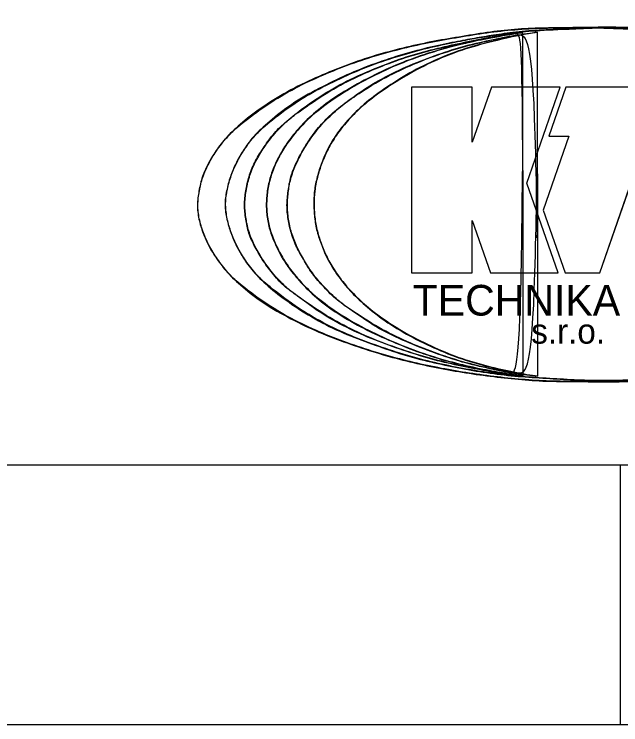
# Model space of a CAD drawing. Extents: x 25 to 46, y -90 to -60.3.
# Drawn here: x 37.705 to 40.036, y -79.8 to -77.068 of the extents above; entities that cross this region are included whole.
import ezdxf

# ---------------------------------------------------------------- set-up
doc = ezdxf.new("R2010")
doc.units = 0
doc.layers.add('_popis', color=7, linetype='Continuous')
doc.layers.add('Rozpiska_pole_6', color=7, linetype='Continuous')

msp = doc.modelspace()

# ---------------------------------------------------------------- linework, layer by layer
at = {"layer": '_popis'}
for p, q in [((39.2313, -77.3488), (39.2313, -78.0628)), ((39.465, -77.3488), (39.2313, -77.3488)), ((39.5386, -77.3488), (39.465, -77.5605)), ((39.465, -77.5605), (39.465, -77.3488)), ((39.8036, -77.3488), (39.5386, -77.3488)), ((39.675, -77.7182), (39.8036, -77.3488)), ((39.825, -77.3488), (39.7594, -77.5375)), ((40.2641, -77.3488), (39.825, -77.3488)), ((39.8369, -77.5375), (39.7381, -77.8213)), ((39.7594, -77.5375), (39.8369, -77.5375)), ((39.9551, -78.0628), (40.1379, -77.5375)), ((39.795, -78.0628), (39.675, -77.7182)), ((39.7381, -77.8213), (39.8222, -78.0628)), ((39.465, -78.0628), (39.465, -77.8616)), ((39.465, -77.8616), (39.535, -78.0628)), ((39.2313, -78.0628), (39.465, -78.0628)), ((39.535, -78.0628), (39.795, -78.0628)), ((39.8222, -78.0628), (39.9551, -78.0628))]:
    msp.add_line(p, q, dxfattribs=at)
for points in [[(39.2313, -77.3488), (39.2313, -78.0628), (39.465, -78.0628), (39.465, -77.8616), (39.535, -78.0628), (39.795, -78.0628), (39.675, -77.7182), (39.8036, -77.3488), (39.5386, -77.3488), (39.465, -77.5605), (39.465, -77.3488), (39.2313, -77.3488)], [(39.825, -77.3488), (39.7594, -77.5375), (39.8369, -77.5375), (39.7381, -77.8213), (39.8222, -78.0628), (39.9551, -78.0628), (40.1379, -77.5375), (40.1984, -77.5375), (40.2641, -77.3488), (39.825, -77.3488)]]:
    msp.add_lwpolyline(points, dxfattribs=at)
for points in [[(39.9639, -77.1182), (39.9235, -77.1188), (39.852, -77.1199), (39.7448, -77.1208), (39.642, -77.1242), (39.5347, -77.1357), (39.4277, -77.1537), (39.3201, -77.1713), (39.2128, -77.1946), (39.1051, -77.2223), (38.9975, -77.2573), (38.8906, -77.3005), (38.7817, -77.3493), (38.6736, -77.4136), (38.589, -77.4768), (38.5246, -77.5353), (38.4849, -77.5846), (38.452, -77.639), (38.4265, -77.6924), (38.4148, -77.7474), (38.4067, -77.8011), (38.4133, -77.8559), (38.4303, -77.9096), (38.4542, -77.9643), (38.4893, -78.0177), (38.5268, -78.0666), (38.5904, -78.1238), (38.6724, -78.1873), (38.7823, -78.2472), (38.8896, -78.2978), (38.9979, -78.3377), (39.1054, -78.3729), (39.2125, -78.4023), (39.3197, -78.4256), (39.427, -78.4454), (39.5348, -78.4603), (39.6419, -78.4721), (39.7493, -78.4805), (39.8565, -78.4792), (39.9639, -78.483), (40.0712, -78.4798), (40.1532, -78.4786), (40.1993, -78.4763), (40.2097, -78.4757)], [(39.9639, -77.1182), (39.8427, -77.1199), (39.7495, -77.1211), (39.6423, -77.1255), (39.5351, -77.1368), (39.4279, -77.1536), (39.3205, -77.1722), (39.2133, -77.1952), (39.1061, -77.2232), (38.9987, -77.2583), (38.8915, -77.3009), (38.7849, -77.3503), (38.6775, -77.4138), (38.5703, -77.4945), (38.5286, -77.5334), (38.4849, -77.5873), (38.4523, -77.6406), (38.4282, -77.6944), (38.4153, -77.7478), (38.4091, -77.8015), (38.4147, -77.8543), (38.431, -77.9085), (38.4551, -77.9623), (38.4888, -78.0156), (38.532, -78.0694), (38.5702, -78.1052), (38.6774, -78.1865), (38.7846, -78.2471), (38.8906, -78.2964), (38.9989, -78.3373), (39.1065, -78.3723), (39.2131, -78.4014), (39.3197, -78.425), (39.4275, -78.4446), (39.535, -78.4598), (39.6427, -78.4716), (39.7487, -78.4789), (39.8568, -78.4801), (39.9639, -78.4818), (40.0711, -78.4801), (40.1786, -78.4773), (40.2858, -78.4705), (40.3924, -78.4605), (40.4999, -78.4442), (40.6071, -78.4251), (40.7143, -78.401), (40.8218, -78.3713), (40.929, -78.336), (41.0362, -78.2945), (41.1428, -78.2446), (41.2508, -78.1813), (41.3585, -78.0978), (41.3905, -78.0692), (41.4326, -78.0159), (41.468, -77.9626), (41.4928, -77.9085), (41.5102, -77.8552), (41.5187, -77.8015), (41.5124, -77.748), (41.4939, -77.6942), (41.4698, -77.6394), (41.4378, -77.5872), (41.3924, -77.5334), (41.3593, -77.5009), (41.2509, -77.417), (41.1437, -77.3537), (41.0373, -77.3029), (40.9295, -77.2614), (40.8218, -77.2244), (40.7152, -77.1964), (40.6071, -77.1722), (40.4994, -77.1537), (40.3917, -77.1386), (40.2853, -77.125), (40.1784, -77.1211), (40.0713, -77.1192), (39.9639, -77.1182), (39.9639, -77.1182), (39.9639, -77.1182)], [(40.2097, -78.4757), (40.235, -78.4743), (40.296, -78.4699), (40.3931, -78.4618), (40.5, -78.4443), (40.6076, -78.426), (40.715, -78.4017), (40.8225, -78.3721), (40.93, -78.3366), (41.0376, -78.2954), (41.1457, -78.2449), (41.256, -78.1823), (41.3346, -78.1179), (41.398, -78.0648), (41.4318, -78.0169), (41.4691, -77.965), (41.4932, -77.9098), (41.5113, -77.8562), (41.5216, -77.8018), (41.5143, -77.7463), (41.4938, -77.6932), (41.471, -77.6383), (41.4374, -77.5837), (41.3984, -77.5387), (41.3381, -77.4793), (41.2557, -77.4172), (41.1464, -77.3533), (41.0387, -77.3015), (40.9301, -77.2615), (40.8235, -77.2229), (40.7151, -77.1961), (40.6078, -77.1712), (40.4996, -77.1531), (40.3922, -77.1391), (40.2856, -77.1225), (40.1783, -77.1213), (40.0712, -77.119), (39.9997, -77.1184), (39.9639, -77.1182)], [(39.9639, -77.1211), (39.9997, -77.1226), (40.0713, -77.1255), (40.1787, -77.1265), (40.2858, -77.1383), (40.393, -77.1519), (40.5005, -77.1698), (40.6076, -77.1935), (40.7158, -77.2191), (40.8227, -77.2556), (40.9309, -77.2969), (41.0378, -77.3497), (41.1493, -77.4096), (41.2316, -77.4752), (41.2925, -77.5363), (41.331, -77.5848), (41.364, -77.639), (41.3885, -77.6928), (41.4013, -77.7476), (41.406, -77.8017), (41.4019, -77.8563), (41.3856, -77.9101), (41.3615, -77.9642), (41.3273, -78.0178), (41.2909, -78.0655), (41.2291, -78.1234), (41.1493, -78.1893), (41.0386, -78.2517), (40.9304, -78.3018), (40.8228, -78.3436), (40.715, -78.3773), (40.6078, -78.4072), (40.5001, -78.4295), (40.393, -78.4491), (40.2855, -78.4596), (40.1784, -78.4688), (40.0713, -78.4757), (39.9639, -78.4792), (39.8566, -78.4751), (39.7494, -78.4675), (39.6419, -78.4616), (39.5346, -78.4489), (39.4272, -78.4315), (39.3199, -78.4087), (39.2119, -78.3821), (39.1053, -78.3453), (38.9969, -78.3064), (38.8884, -78.2571), (38.7805, -78.1918), (38.696, -78.1276), (38.6313, -78.0686), (38.5928, -78.0182), (38.5608, -77.9637), (38.5367, -77.9099), (38.5218, -77.8558), (38.5123, -77.8015), (38.5206, -77.7471), (38.5345, -77.693), (38.5572, -77.6389), (38.589, -77.5849), (38.6276, -77.5322), (38.6946, -77.4726), (38.7792, -77.4054), (38.8901, -77.3461), (38.997, -77.2943), (39.1048, -77.2523), (39.2124, -77.218), (39.32, -77.1904), (39.4116, -77.1723), (39.4832, -77.1591), (39.5546, -77.1477), (39.6419, -77.1348), (39.7494, -77.1281), (39.8567, -77.1236), (39.9282, -77.122), (39.9639, -77.1211)], [(39.9639, -77.1211), (39.8567, -77.124), (39.7495, -77.1284), (39.6423, -77.1363), (39.5351, -77.1509), (39.4869, -77.1587), (39.428, -77.1694), (39.3205, -77.1913), (39.2133, -77.2188), (39.1059, -77.2532), (38.9988, -77.2952), (38.8914, -77.3463), (38.7848, -77.4063), (38.6775, -77.4883), (38.6298, -77.5333), (38.5888, -77.5872), (38.558, -77.6404), (38.5355, -77.6944), (38.5215, -77.7477), (38.5153, -77.8015), (38.5226, -77.8551), (38.5377, -77.9083), (38.5613, -77.9622), (38.5928, -78.0158), (38.6349, -78.0696), (38.6775, -78.11), (38.7847, -78.1919), (38.8914, -78.256), (38.9986, -78.3054), (39.1058, -78.3452), (39.2132, -78.3807), (39.3204, -78.4082), (39.4276, -78.4306), (39.535, -78.4482), (39.6422, -78.4605), (39.7494, -78.4678), (39.8567, -78.4745), (39.9639, -78.4779), (40.0711, -78.4751), (40.1786, -78.4684), (40.2852, -78.4594), (40.3924, -78.4476), (40.4999, -78.4291), (40.607, -78.4061), (40.7142, -78.3769), (40.8217, -78.3426), (40.9289, -78.3011), (41.0361, -78.2512), (41.1435, -78.1886), (41.2507, -78.1028), (41.285, -78.0695), (41.3277, -78.0156), (41.3608, -77.9624), (41.3849, -77.9085), (41.4, -77.8553), (41.4045, -77.802), (41.4, -77.7479), (41.3871, -77.6947), (41.3636, -77.6408), (41.331, -77.5872), (41.2883, -77.5333), (41.2507, -77.4952), (41.1436, -77.4105), (41.0362, -77.3496), (40.929, -77.298), (40.8218, -77.256), (40.7144, -77.2206), (40.6073, -77.1937), (40.5001, -77.1707), (40.3926, -77.1526), (40.2855, -77.1385), (40.1786, -77.1283), (40.0714, -77.1249), (39.9639, -77.1211), (39.9639, -77.1211), (39.9639, -77.1211)], [(39.6602, -78.458), (39.6397, -78.4563), (39.5976, -78.4528), (39.5198, -78.4409), (39.4269, -78.4217), (39.3184, -78.3987), (39.2116, -78.3644), (39.1038, -78.3273), (38.9959, -78.2806), (38.8864, -78.2219), (38.8103, -78.1619), (38.7425, -78.1172), (38.7024, -78.072), (38.6615, -78.0175), (38.6297, -77.9637), (38.605, -77.9105), (38.5941, -77.8555), (38.5881, -77.8016), (38.5939, -77.7473), (38.6063, -77.6931), (38.6272, -77.6379), (38.6605, -77.5856), (38.6988, -77.5289), (38.7427, -77.4867), (38.8068, -77.4345), (38.8874, -77.3779), (38.9961, -77.3167), (39.1047, -77.2712), (39.2116, -77.2305), (39.3197, -77.2014), (39.4279, -77.1771), (39.5349, -77.1558), (39.6124, -77.142), (39.6542, -77.1395), (39.6598, -77.1392)], [(39.6602, -78.458), (39.5987, -78.4522), (39.5345, -78.4427), (39.4273, -78.4217), (39.3195, -78.397), (39.212, -78.3641), (39.1053, -78.3263), (38.9986, -78.2801), (38.891, -78.2205), (38.7832, -78.1443), (38.7543, -78.1238), (38.7017, -78.0697), (38.6611, -78.0148), (38.6301, -77.9622), (38.6069, -77.9092), (38.5948, -77.8548), (38.59, -77.8012), (38.5948, -77.7486), (38.6074, -77.694), (38.6284, -77.64), (38.66, -77.587), (38.6984, -77.5334), (38.753, -77.4787), (38.7825, -77.4546), (38.891, -77.3782), (38.9993, -77.3178), (39.1062, -77.2713), (39.2118, -77.2324), (39.3215, -77.2018), (39.4277, -77.1776), (39.5355, -77.1561), (39.643, -77.1403), (39.6598, -77.1392), (39.6602, -78.458), (39.6598, -77.1392)], [(39.6598, -77.1392), (39.6211, -77.145), (39.5434, -77.1566), (39.4299, -77.18), (39.3193, -77.2104), (39.2112, -77.2461), (39.1041, -77.2935), (38.9959, -77.3501), (38.9011, -77.412), (38.8266, -77.4743), (38.7771, -77.5313), (38.7382, -77.5846), (38.7093, -77.6388), (38.6886, -77.693), (38.6762, -77.7474), (38.6726, -77.8018), (38.6765, -77.8558), (38.6901, -77.9101), (38.7131, -77.9634), (38.7413, -78.0185), (38.7818, -78.0714), (38.8307, -78.127), (38.9025, -78.1891), (38.9959, -78.2499), (39.1046, -78.3045), (39.2124, -78.3503), (39.3194, -78.3886), (39.4271, -78.4174), (39.5243, -78.4371), (39.6021, -78.4501), (39.6439, -78.4558), (39.6602, -78.458)], [(39.6598, -77.1392), (39.5441, -77.1576), (39.4279, -77.1817), (39.3201, -77.2112), (39.2125, -77.2476), (39.1063, -77.2938), (38.9991, -77.3506), (38.8916, -77.4218), (38.8243, -77.4796), (38.7764, -77.5337), (38.7386, -77.5868), (38.7102, -77.6399), (38.6896, -77.6943), (38.6775, -77.7484), (38.6738, -77.8014), (38.678, -77.8554), (38.6912, -77.9085), (38.7133, -77.9621), (38.7422, -78.0162), (38.7811, -78.0693), (38.829, -78.1228), (38.8926, -78.1785), (38.9988, -78.2489), (39.1066, -78.3041), (39.2136, -78.3496), (39.3208, -78.3874), (39.4276, -78.4163), (39.5351, -78.4385), (39.6113, -78.4511), (39.6602, -78.458), (39.6598, -77.1392), (39.6602, -78.458)], [(39.7161, -78.4596), (39.6914, -78.4575), (39.6304, -78.4523), (39.5347, -78.4318), (39.4265, -78.4074), (39.3198, -78.3704), (39.2116, -78.3288), (39.1018, -78.2769), (39.021, -78.2196), (38.9493, -78.1723), (38.9019, -78.1253), (38.8532, -78.0728), (38.8201, -78.0165), (38.7893, -77.964), (38.7686, -77.9101), (38.7572, -77.8559), (38.7513, -77.8017), (38.7578, -77.7476), (38.7662, -77.6929), (38.7884, -77.6393), (38.817, -77.5858), (38.8518, -77.5308), (38.8972, -77.476), (38.9485, -77.4304), (39.0183, -77.3777), (39.1027, -77.3224), (39.2113, -77.2692), (39.3191, -77.2272), (39.4263, -77.1919), (39.5343, -77.1674), (39.6305, -77.1475), (39.6915, -77.1406), (39.7161, -77.1377)], [(39.7161, -78.4596), (39.6424, -78.452), (39.5346, -78.4316), (39.4284, -78.4058), (39.3206, -78.3701), (39.2131, -78.3279), (39.1064, -78.2754), (38.9989, -78.2052), (38.9585, -78.1768), (38.9001, -78.1227), (38.8538, -78.0696), (38.8196, -78.0157), (38.7902, -77.9621), (38.7697, -77.9085), (38.7581, -77.856), (38.7533, -77.8017), (38.7581, -77.7475), (38.7681, -77.6945), (38.7886, -77.6412), (38.8175, -77.5866), (38.8517, -77.5335), (38.8964, -77.4796), (38.9552, -77.426), (38.9994, -77.3924), (39.1063, -77.3233), (39.213, -77.2702), (39.3208, -77.2277), (39.4272, -77.1935), (39.5345, -77.1677), (39.6424, -77.1471), (39.7161, -77.1377), (39.7161, -78.4596), (39.7161, -77.1377)], [(39.7161, -77.1377), (39.6915, -77.1413), (39.6306, -77.1502), (39.5345, -77.1738), (39.426, -77.2027), (39.3179, -77.2449), (39.2101, -77.3004), (39.1156, -77.3622), (39.0382, -77.4217), (38.9841, -77.4775), (38.9415, -77.531), (38.9092, -77.5853), (38.8859, -77.6396), (38.8686, -77.6935), (38.8574, -77.7474), (38.8558, -77.8015), (38.8589, -77.8555), (38.8693, -77.9097), (38.8885, -77.9631), (38.9121, -78.0178), (38.946, -78.0711), (38.9886, -78.1254), (39.0426, -78.1786), (39.1162, -78.2399), (39.21, -78.2985), (39.3183, -78.352), (39.4258, -78.3958), (39.5342, -78.4259), (39.631, -78.446), (39.6914, -78.4557), (39.7161, -78.4596)], [(39.7161, -77.1377), (39.6424, -77.1494), (39.5353, -77.174), (39.4276, -77.2044), (39.3205, -77.2459), (39.2132, -77.3011), (39.1061, -77.3706), (39.0357, -77.4266), (38.9836, -77.4798), (38.9415, -77.5336), (38.9099, -77.5869), (38.8865, -77.6407), (38.8694, -77.6943), (38.8589, -77.7481), (38.8565, -77.8013), (38.86, -77.8551), (38.8706, -77.9089), (38.8887, -77.9621), (38.9128, -78.0157), (38.9461, -78.0695), (38.9877, -78.1221), (39.0416, -78.1762), (39.106, -78.2294), (39.213, -78.2978), (39.3203, -78.3513), (39.4274, -78.394), (39.5356, -78.425), (39.6423, -78.4473), (39.7161, -78.4596), (39.7161, -77.1377), (39.7161, -78.4596)]]:
    msp.add_open_spline(points, degree=3, dxfattribs=at)
at = {"layer": 'Rozpiska_pole_6'}
for p, q in [((27, -78.8), (44, -78.8)), ((40.035, -79.8), (40.035, -78.8))]:
    msp.add_line(p, q, dxfattribs=at)
msp.add_lwpolyline([(27, -74.8), (44, -74.8), (44, -79.8), (27, -79.8)], close=True, dxfattribs=at)

# ---------------------------------------------------------------- texts
at = {"layer": '_popis'}
for s, height, p in [('TECHNIKA', 0.11795, (39.2362, -78.2268)), ('s.r.o.', 0.09543, (39.6919, -78.3347))]:
    msp.add_text(s, height=height, dxfattribs=at).set_placement(p)

doc.saveas('drawing.dxf')
